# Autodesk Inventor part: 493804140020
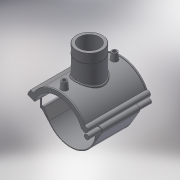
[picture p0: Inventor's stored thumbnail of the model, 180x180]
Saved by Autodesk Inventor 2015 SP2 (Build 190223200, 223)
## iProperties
Created: 2017-07
Part Number: 493804140020
Material: Generic
Description: PLASSON TRANSITION SADDLE 140-2"
Document SubType Name: Modeling
Designer: KIM
Density: 1 g/cm^3
Appearance: Default
Author: KIM
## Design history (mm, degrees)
derived "493804.ipt"
feature "Solid1::493804.ipt"
tag "TaggingFeature1"
body "Solid1"
other parameters: "d1" = 161, "d2" = 174, "d3" = 35, "d4" = 176, "d5" = 0, "d6" = 0.1, "d8" = 0, "d19" = 6, "d20" = 6, "d21" = 105.6, "d23" = 0, "d24" = 52.8, "d26" = 0, "d27" = 3, "d28" = 3, "d29" = 3, "d30" = 46.66667, "d31" = 6, "d32" = 0, "d33" = 0, "d34" = 0.6, "d40" = 83.72, "d41" = 79.3184, "d43" = 0, "d45" = 0, "d47" = 156.5, "d48" = 73.6528, "d50" = 0, "d70" = 15, "d72" = 0, "d73" = 6, "d75" = 5, "d76" = 0, "d77" = 7, "d79" = 15, "d80" = 70.4, "d82" = 5 deg, "d84" = 4, "d85" = 14, "d86" = 0, "d87" = 3, "d88" = 0, "d89" = 1, "d90" = 1, "d91" = 140.8, "d92" = 0, "d93" = 0.5, "d94" = 73.68421, "d96" = 164.22, "d97" = 3.52, "d98" = 0, "d102" = 1.69968, "d103" = 56.656, "d104" = 45.6, "d105" = 0, "d106" = 45.3248, "d108" = 0, "d109" = -25.33333, "d111" = 0.5, "d112" = 0.5, "d113" = 0, "d114" = 0.5, "d117" = 0.56656, "d120" = 140 deg, "d121" = 24.228, "d122" = 20 deg, "d123" = 322, "d124" = 96.6, "d126" = 0, "d143" = 144.2, "d145" = 16.15385, "d149" = 2.1, "d150" = 17.76923, "d153" = 176, "d154" = 0, "d156" = 80.5, "d157" = 160 deg, "d159" = 4.2, "d161" = 2.1, "d162" = 105.6, "d163" = 0, "d167" = 14, "d168" = 78.53659, "d170" = 2.1, "d172" = 0, "d173" = 1, "d176" = 20 deg, "d177" = 9.8, "d178" = 21, "d180" = 0, "d183" = 8.4, "d184" = 7.84, "d185" = 57.2, "d186" = 57.2, "d187" = 80.5, "d188" = 6.3, "d189" = 9.8, "d190" = 0, "d191" = 96.6, "d193" = 4.2, "d194" = 4.4, "d195" = 90 deg, "d197" = 0, "d199" = 0, "B_" = 174, "H_" = 76, "L_" = 176, "d_t" = 6, "G_" = 56.656, "d148" = 2.1, "d160" = 2.1, "d169" = 2.1, "d192" = 4.2
